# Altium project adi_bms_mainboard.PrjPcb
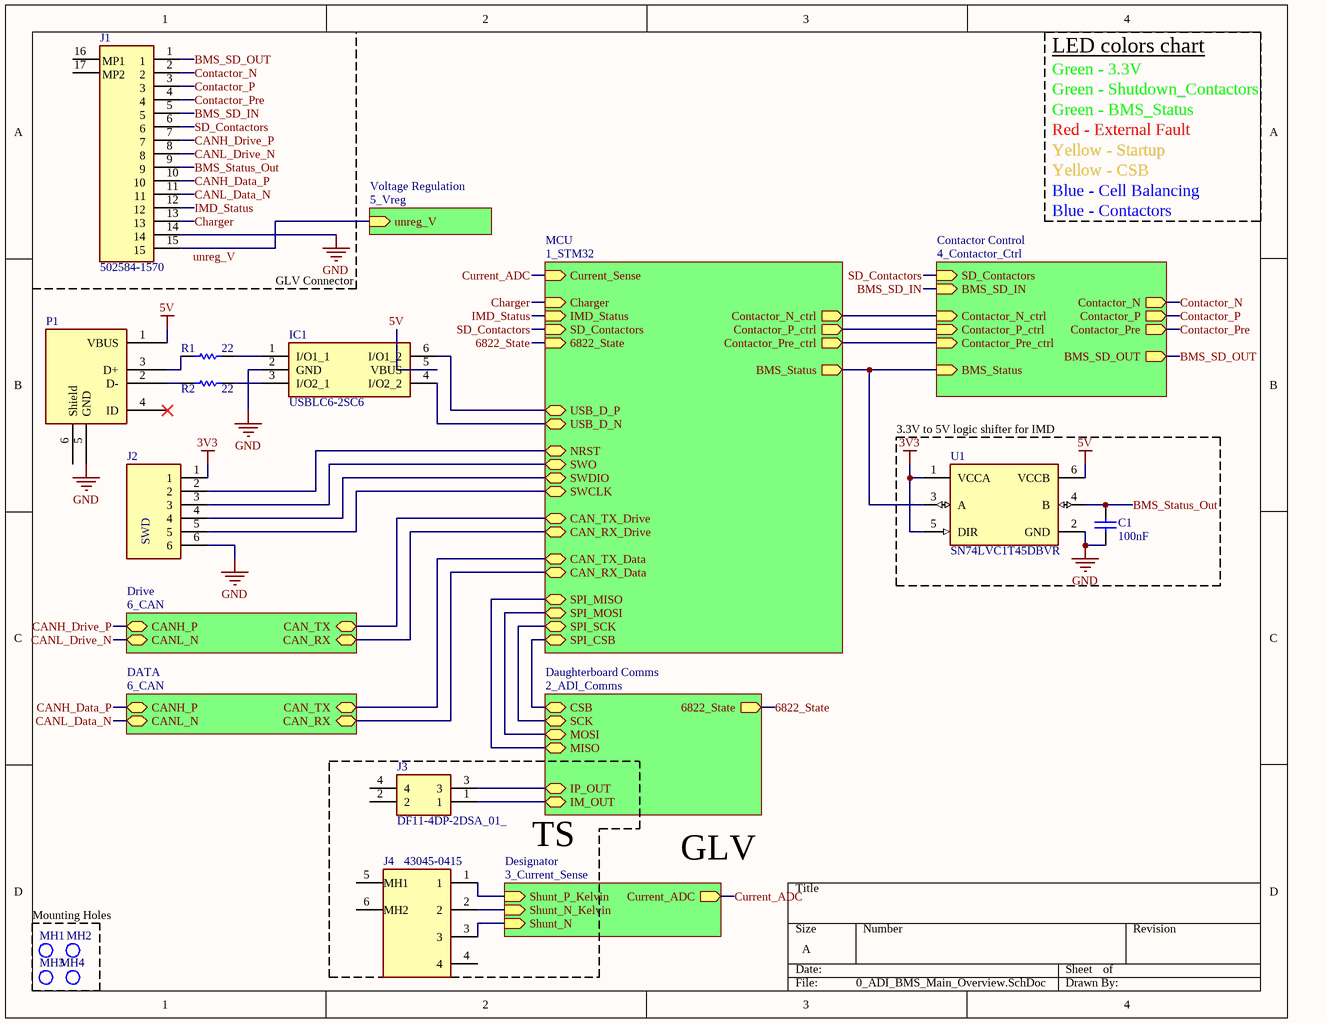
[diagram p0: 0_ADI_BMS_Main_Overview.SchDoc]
7 sheets, 187 parts. Net scope: hierarchical (ports join the sheet entries above them; power ports are global).
Board file: ad_mainboard.PcbDoc
Sheets:
  0_ADI_BMS_Main_Overview.SchDoc
    MCU = 1_STM32.SchDoc
    Contactor Control = 4_Contactor_Ctrl.SchDoc
    Daughterboard Comms = 2_ADI_Comms.SchDoc
    Designator = 3_Current_Sense.SchDoc
    Voltage Regulation = 5_Vreg.SchDoc
    Drive = 6_CAN.SchDoc
    DATA = 6_CAN.SchDoc

## Sheet 0_ADI_BMS_Main_Overview.SchDoc
size A

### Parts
C1  value 100nF  [CAPC0603(1608)100_L]  (hidden comment: CGA3E2X7R1H104K080AA)
IC1  USBLC6-2SC6  [SOT95P280X145-6N]
J1  502584-1570  [FP-502584-1570-MFG]
J2  61300611121  [HDRV6W64P0X254_1X6_1524X254X869P]  (value not drawn)
J3  DF11-4DP-2DSA_01_  [SHDR4W50P200_2X2_600X500X660P]
J4  43045-0415  [FP-43045-0415-MFG]
MH1  Mounting Hole 6-32 Non Plated  [Mounting Hole 6-32-Footprint-1]  (value not drawn)
MH2  Mounting Hole 6-32 Non Plated  [Mounting Hole 6-32-Footprint-1]  (value not drawn)
MH3  Mounting Hole 6-32 Non Plated  [Mounting Hole 6-32-Footprint-1]  (value not drawn)
MH4  Mounting Hole 6-32 Non Plated  [Mounting Hole 6-32-Footprint-1]  (value not drawn)
P1  1051640001  [1051640001-Footprint-1]  (value not drawn)
R1  value 22  [RESC0603(1608)_L]  (hidden comment: RC0603FR-0722RL)
R2  value 22  [RESC0603(1608)_L]  (hidden comment: RC0603FR-0722RL)
U1  SN74LVC1T45DBVR  [FP-DBV0006A-IPC_B]

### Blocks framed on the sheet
3.3V to 5V logic shifter for IMD: C1 U1
TS: J3 J4
Mounting Holes: MH1-MH4

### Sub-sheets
Contactor Control = 4_Contactor_Ctrl: SD_Contactors (in), Contactor_N_ctrl (in), Contactor_P_ctrl (in), Contactor_Pre_ctrl (in), BMS_Status (in), Contactor_N (out), Contactor_P (out), Contactor_Pre (out), BMS_SD_OUT (out), BMS_SD_IN (in)
DATA = 6_CAN: CAN_TX (bidir), CAN_RX (bidir), CANH_P (bidir), CANL_N (bidir)
Daughterboard Comms = 2_ADI_Comms: MISO (bidir), MOSI (bidir), SCK (bidir), CSB (bidir), 6822_State (out), IP_OUT (bidir), IM_OUT (bidir)
Designator = 3_Current_Sense: Shunt_P_Kelvin (in), Shunt_N_Kelvin (in), Shunt_N (in), Current_ADC (out)
Drive = 6_CAN: CAN_TX (bidir), CAN_RX (bidir), CANH_P (bidir), CANL_N (bidir)
MCU = 1_STM32: Current_Sense (in), Charger (in), IMD_Status (in), SD_Contactors (in), 6822_State (in), NRST (bidir), USB_D_N (bidir), USB_D_P (bidir), SWDIO (bidir), SWCLK (bidir), SWO (bidir), CAN_TX_Drive (bidir), CAN_RX_Drive (bidir), CAN_TX_Data (bidir), CAN_RX_Data (bidir), SPI_MISO (bidir), SPI_MOSI (bidir), SPI_SCK (bidir), SPI_CSB (bidir), BMS_Status (out), Contactor_N_ctrl (out), Contactor_P_ctrl (out), Contactor_Pre_ctrl (out)
Voltage Regulation = 5_Vreg: unreg_V (in)

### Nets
3V3: J2.1 U1.1(VCCA) U1.5(DIR)
5V: IC1.5(VBUS) P1.1(VBUS) U1.6(VCCB)
GND: C1.2 IC1.2(GND) J1.14 J2.6 P1.5(GND) U1.2(GND)
6822_State: sheet MCU/6822_State, sheet Daughterboard Comms/6822_State
BMS_SD_IN: J1.5 ; sheet Contactor Control/BMS_SD_IN
BMS_SD_OUT: J1.1 ; sheet Contactor Control/BMS_SD_OUT
BMS_Status: U1.3(A) ; sheet MCU/BMS_Status, sheet Contactor Control/BMS_Status
BMS_Status_Out: C1.1 J1.9 U1.4(B)
CAN_RX: sheet MCU/CAN_RX_Data, sheet DATA/CAN_RX
CAN_RX: sheet MCU/CAN_RX_Drive, sheet Drive/CAN_RX  [a separate net that carries the same name]
CAN_TX: sheet MCU/CAN_TX_Data, sheet DATA/CAN_TX
CAN_TX: sheet MCU/CAN_TX_Drive, sheet Drive/CAN_TX  [a separate net that carries the same name]
CANH_Data_P: J1.10 ; sheet DATA/CANH_P
CANH_Drive_P: J1.7 ; sheet Drive/CANH_P
CANL_Data_N: J1.11 ; sheet DATA/CANL_N
CANL_Drive_N: J1.8 ; sheet Drive/CANL_N
Charger: J1.13 ; sheet MCU/Charger
Contactor_N: J1.2 ; sheet Contactor Control/Contactor_N
Contactor_N_ctr: sheet MCU/Contactor_N_ctrl, sheet Contactor Control/Contactor_N_ctrl
Contactor_P: J1.3 ; sheet Contactor Control/Contactor_P
Contactor_P_ctrl: sheet MCU/Contactor_P_ctrl, sheet Contactor Control/Contactor_P_ctrl
Contactor_Pre: J1.4 ; sheet Contactor Control/Contactor_Pre
Contactor_Pre_ctr: sheet MCU/Contactor_Pre_ctrl, sheet Contactor Control/Contactor_Pre_ctrl
CSB: sheet MCU/SPI_CSB, sheet Daughterboard Comms/CSB
Current_ADC: sheet MCU/Current_Sense, sheet Designator/Current_ADC
IM_Out: J3.1 ; sheet Daughterboard Comms/IM_OUT
IMD_Status: J1.12 ; sheet MCU/IMD_Status
IP_Out: J3.3 ; sheet Daughterboard Comms/IP_OUT
MISO: sheet MCU/SPI_MISO, sheet Daughterboard Comms/MISO
MOSI: sheet MCU/SPI_MOSI, sheet Daughterboard Comms/MOSI
NRST: J2.2 ; sheet MCU/NRST
SCK: sheet MCU/SPI_SCK, sheet Daughterboard Comms/SCK
SD_Contactors: J1.6 ; sheet MCU/SD_Contactors, sheet Contactor Control/SD_Contactors
Shunt_N: J4.3 ; sheet Designator/Shunt_N
Shunt_N_Kelvin: J4.2 ; sheet Designator/Shunt_N_Kelvin
Shunt_P_Kelvin: J4.1 ; sheet Designator/Shunt_P_Kelvin
SWCLK: J2.5 ; sheet MCU/SWCLK
SWDIO: J2.4 ; sheet MCU/SWDIO
SWO: J2.3 ; sheet MCU/SWO
unreg_V: J1.15 ; sheet Voltage Regulation/unreg_V
USB_D_N: IC1.4(I/O2_2) ; sheet MCU/USB_D_N
USB_D_P: IC1.6(I/O1_2) ; sheet MCU/USB_D_P
NetIC1_1: IC1.1(I/O1_1) R1.2
NetIC1_3: IC1.3(I/O2_1) R2.2
NetP1_2: P1.2(D-) R2.1
NetP1_3: P1.3(D+) R1.1

Not connected (* = marked no-connect by the designer): J1 16(MNT_1) 17(MNT_2); J3 2 4; J4 4 5(MNT_1) 6(MNT_2); P1 4(ID)* 6(Shield)

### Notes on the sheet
- LED colors chart
- Green - 3.3V
- Green - Shutdown_Contactors
- Red - External Fault
- Green - BMS_Status
- Yellow - Startup
- Blue - Cell Balancing
- Yellow - CSB
- Blue - Contactors
- GLV Connector
- (near J2) SWD
- GLV

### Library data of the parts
C1 = CMP-001-00125-1: Ceramic Capacitor, Multilayer, Ceramic, 50V, 10% +Tol, 10% -Tol, X7R, 15% TC, 0.1uF, Surface Mount, 0603
IC1 = USBLC6-2SC6: Integrated Circuit; Manufacturer_Name: STMicroelectronics
J1 = CMP-002-00103-1: Board Connector, 15 Contact(s), 1 Row(s), Female, Straight, 0.059 inch Pitch, Surface Mount Terminal, Locking, Beige Insulator, Receptacle
J2 = 61300611121: Connector; Manufacturer_Name: Wurth Elektronik
J3 = DF11-4DP-2DSA_01_: Connector; Manufacturer_Name: Hirose; Manufacturer_Part_Number: DF11-4DP-2DSA(01)
J4 = CMP-002-00105-1: Rectangular Power Connector, 4 Contact(s), Male, Surface Mount Terminal, Receptacle; Connector Type: Power,Rectangular
MH1-MH4 = CMP-00028-00008-4: Mounting hole for 6-32 fastener
P1 = CMP-002-00079-1: USB - micro B USB 2.0 Receptacle Connector 5 Position Surface Mount, Right Angle; Through Hole
R1 R2 = CMP-009-00242-1: Fixed Resistor, Metal Glaze/thick Film, 0.1W, 22ohm, 75V, 1% +/-Tol, 100ppm/Cel, Surface Mount, 0603; Power: 100mW
U1 = CMP-0859-00206-4: IC TRNSLTR BIDIRECTIONAL SOT23-6; Number of Inputs: 1; Logic Function: Translator; Min Supply Voltage: 1.65V; Quiescent Current: 3uA; Turn-On Delay Time: 36.2ns; Max Supply Voltage: 5.5V; Polarity: Non-Inverting; Propagation Delay: 3.9ns; Low Level Output Current: 32mA; Data Rate: 420Mbps; High Level Output Current: -32mA

## Sheet 1_STM32.SchDoc
size A
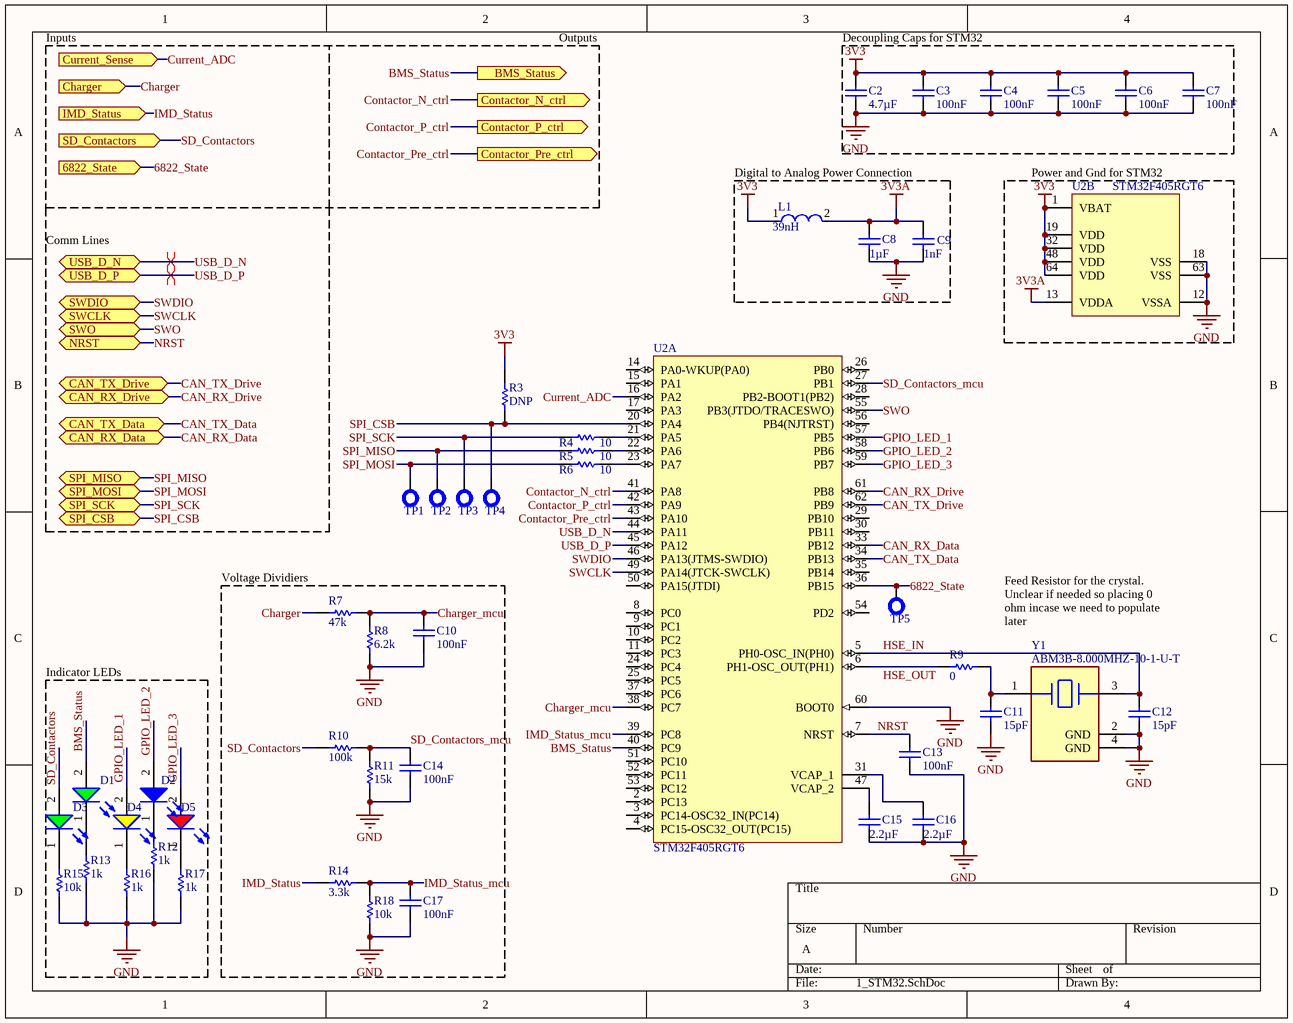
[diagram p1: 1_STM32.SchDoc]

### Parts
C2  value 4.7µF  [CAPC0603(1608)100_L]  (hidden comment: GRT188R6YA475KE13D)
C3  value 100nF  [CAPC0603(1608)100_L]  (hidden comment: CGA3E2X7R1H104K080AA)
C4  value 100nF  [CAPC0603(1608)100_L]  (hidden comment: CGA3E2X7R1H104K080AA)
C5  value 100nF  [CAPC0603(1608)100_L]  (hidden comment: CGA3E2X7R1H104K080AA)
C6  value 100nF  [CAPC0603(1608)100_L]  (hidden comment: CGA3E2X7R1H104K080AA)
C7  value 100nF  [CAPC0603(1608)100_L]  (hidden comment: CGA3E2X7R1H104K080AA)
C8  value 1µF  [CAPC0603(1608)100_L]  (hidden comment: GRT188R61H105KE13D)
C9  1nF  [CAPC0603(1608)100_L]
C10  value 100nF  [CAPC0603(1608)100_L]  (hidden comment: CGA3E2X7R1H104K080AA)
C11  value 15pF  [CAPC0603(1608)100_L]  (hidden comment: CL10C150JB81PNC)
C12  value 15pF  [CAPC0603(1608)100_L]  (hidden comment: CL10C150JB81PNC)
C13  value 100nF  [CAPC0603(1608)100_L]  (hidden comment: CGA3E2X7R1H104K080AA)
C14  value 100nF  [CAPC0603(1608)100_L]  (hidden comment: CGA3E2X7R1H104K080AA)
C15  value 2.2µF  [CAPC0603(1608)100_L]  (hidden comment: CL10Y225KP84PNC)
C16  value 2.2µF  [CAPC0603(1608)100_L]  (hidden comment: CL10Y225KP84PNC)
C17  value 100nF  [CAPC0603(1608)100_L]  (hidden comment: CGA3E2X7R1H104K080AA)
D1  150060VS75000  [WL-SMCW_0603_150060xx75000]  (value not drawn)
D2  150060BS75000  [WL-SMCW_0603_150060xx75000]  (value not drawn)
D3  150060VS75000  [WL-SMCW_0603_150060xx75000]  (value not drawn)
D4  150060YS75000  [WL-SMCW_0603_150060xx75000]  (value not drawn)
D5  150060RS75000  [WL-SMCW_0603_150060xx75000]  (value not drawn)
L1  Inductance: 39nH  [FP-LQW18AN_00-MFG]  (hidden comment: LQW18AN39NJ00D)
R3  value DNP  [RESC0603(1608)_L]  (hidden comment: RT0603BRD0710KL)
R4  value 10  [RESC0603(1608)_L]  (hidden comment: RMCF0603FT10R0)
R5  value 10  [RESC0603(1608)_L]  (hidden comment: RMCF0603FT10R0)
R6  value 10  [RESC0603(1608)_L]  (hidden comment: RMCF0603FT10R0)
R7  value 47k  [RESC0603(1608)_L]  (hidden comment: ERA-3AEB473V)
R8  value 6.2k  [RESC0603(1608)_L]  (hidden comment: ERA-3AEB622V)
R9  value 0  [RESC0603(1608)_L]  (hidden comment: RMCF0603ZT0R00)
R10  value 100k  [RESC0603(1608)_L]  (hidden comment: ERJ-3EKF1003V)
R11  value 15k  [RESC0603(1608)_L]  (hidden comment: ERA-3AEB153V)
R12  value 1k  [RESC0603(1608)_L]  (hidden comment: RMCF0603FT1K00)
R13  value 1k  [RESC0603(1608)_L]  (hidden comment: RMCF0603FT1K00)
R14  value 3.3k  [RESC0603(1608)_L]  (hidden comment: ERA-3AEB332V)
R15  value 10k  [RESC0603(1608)_L]  (hidden comment: RT0603BRD0710KL)
R16  value 1k  [RESC0603(1608)_L]  (hidden comment: RMCF0603FT1K00)
R17  value 1k  [RESC0603(1608)_L]  (hidden comment: RMCF0603FT1K00)
R18  value 10k  [RESC0603(1608)_L]  (hidden comment: RT0603BRD0710KL)
TP1  TEST_POINT_40_MIL  [TEST_POINT_40_MIL-Footprint-1]  (value not drawn)
TP2  TEST_POINT_40_MIL  [TEST_POINT_40_MIL-Footprint-1]  (value not drawn)
TP3  TEST_POINT_40_MIL  [TEST_POINT_40_MIL-Footprint-1]  (value not drawn)
TP4  TEST_POINT_40_MIL  [TEST_POINT_40_MIL-Footprint-1]  (value not drawn)
TP5  TEST_POINT_40_MIL  [TEST_POINT_40_MIL-Footprint-1]  (value not drawn)
U2  STM32F405RGT6  [STM-LQFP64_M]  (parts A,B of 2)
Y1  ABM3B-8.000MHZ-10-1-U-T  [FP-ABM3B-MFG]

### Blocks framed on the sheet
Decoupling Caps for STM32: C2-C7
Digital to Analog Power Connection: C8 C9 L1
Power and Gnd for STM32: U2
Voltage Dividiers: C10 C14 C17 R7 R8 R10 R11 R14 R18
Indicator LEDs: D1-D5 R12 R13 R15-R17

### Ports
6822_State (in), BMS_Status (out), CAN_RX_Data (bidir), CAN_RX_Drive (bidir), CAN_TX_Data (bidir), CAN_TX_Drive (bidir), Charger (in), Contactor_N_ctrl (out), Contactor_P_ctrl (out), Contactor_Pre_ctrl (out), Current_Sense (in), IMD_Status (in), NRST (bidir), SD_Contactors (in), SPI_CSB (bidir), SPI_MISO (bidir), SPI_MOSI (bidir), SPI_SCK (bidir), SWCLK (bidir), SWDIO (bidir), SWO (bidir), USB_D_N (bidir), USB_D_P (bidir)

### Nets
3V3: C2.2 C3.1 C4.1 C5.1 C6.1 C7.1 L1.1 R3.2 U2.1(VBAT) U2.19(VDD) U2.32(VDD) U2.48(VDD) U2.64(VDD)
3V3A: C8.2 C9.2 L1.2 U2.13(VDDA)
GND: C2.1 C3.2 C4.2 C5.2 C6.2 C7.2 C8.1 C9.1 C10.2 C11.1 C12.1 C13.2 C14.2 C15.2 C16.2 C17.2 R8.2 R11.1 R12.1 R13.1 R15.1 R16.1 R17.1 R18.1 U2.12(VSSA) U2.18(VSS) U2.60(BOOT0) U2.63(VSS) Y1.2(GND) Y1.4(GND)
6822_State: TP5.1 U2.36(PB15) ; port 6822_State
BMS_Status: D1.2(A) U2.40(PC9) ; port BMS_Status
CAN_RX_Data: U2.33(PB12) ; port CAN_RX_Data  [project net CAN_RX]
CAN_RX_Drive: U2.61(PB8) ; port CAN_RX_Drive  [project net CAN_RX]
CAN_TX_Data: U2.34(PB13) ; port CAN_TX_Data  [project net CAN_TX]
CAN_TX_Drive: U2.62(PB9) ; port CAN_TX_Drive  [project net CAN_TX]
Charger: R7.2 ; port Charger
Charger_mcu: C10.1 R7.1 R8.1 U2.38(PC7)
Contactor_N_ctrl: U2.41(PA8) ; port Contactor_N_ctrl  [project net Contactor_N_ctr]
Contactor_P_ctrl: U2.42(PA9) ; port Contactor_P_ctrl
Contactor_Pre_ctrl: U2.43(PA10) ; port Contactor_Pre_ctrl  [project net Contactor_Pre_ctr]
Current_ADC: U2.16(PA2) ; port Current_Sense
GPIO_LED_1: D4.2(A) U2.57(PB5)
GPIO_LED_2: D2.2(A) U2.58(PB6)
GPIO_LED_3: D5.2(A) U2.59(PB7)
HSE_IN: C12.2 U2.5(PH0-OSC_IN(PH0)) Y1.3
HSE_OUT: R9.2 U2.6(PH1-OSC_OUT(PH1))
IMD_Status: R14.2 ; port IMD_Status
IMD_Status_mcu: C17.1 R14.1 R18.2 U2.39(PC8)
NRST: C13.1 U2.7(NRST) ; port NRST
SD_Contactors: D3.2(A) R10.1 ; port SD_Contactors
SD_Contactors_mcu: C14.1 R10.2 R11.2 U2.27(PB1)
SPI_CSB: R3.1 TP4.1 U2.20(PA4) ; port SPI_CSB  [project net CSB]
SPI_MISO: R5.1 TP2.1 ; port SPI_MISO  [project net MISO]
SPI_MOSI: R6.1 TP1.1 ; port SPI_MOSI  [project net MOSI]
SPI_SCK: R4.1 TP3.1 ; port SPI_SCK  [project net SCK]
SWCLK: U2.49(PA14(JTCK-SWCLK)) ; port SWCLK
SWDIO: U2.46(PA13(JTMS-SWDIO)) ; port SWDIO
SWO: U2.55(PB3(JTDO/TRACESWO)) ; port SWO
USB_D_N: U2.44(PA11) ; port USB_D_N
USB_D_P: U2.45(PA12) ; port USB_D_P
NetC11_2: C11.2 R9.1 Y1.1
NetC15_1: C15.1 U2.47(VCAP_2)
NetC16_1: C16.1 U2.31(VCAP_1)
NetD1_1: D1.1(K) R13.2
NetD2_1: D2.1(K) R12.2
NetD3_1: D3.1(K) R15.2
NetD4_1: D4.1(K) R16.2
NetD5_1: D5.1(K) R17.2
NetR4_2: R4.2 U2.21(PA5)
NetR5_2: R5.2 U2.22(PA6)
NetR6_2: R6.2 U2.23(PA7)

Not connected (* = marked no-connect by the designer): U2 2(PC13) 3(PC14-OSC32_IN(PC14)) 4(PC15-OSC32_OUT(PC15)) 8(PC0) 9(PC1) 10(PC2) 11(PC3) 14(PA0-WKUP(PA0)) 15(PA1) 17(PA3) 24(PC4) 25(PC5) 26(PB0) 28(PB2-BOOT1(PB2)) 29(PB10) 30(PB11) 35(PB14) 37(PC6) 50(PA15(JTDI)) 51(PC10) 52(PC11) 53(PC12) 54(PD2) 56(PB4(NJTRST))

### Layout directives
differential pair: USB_D_N, USB_D_P

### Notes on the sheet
- Inputs
- Outputs
- Comm Lines
- Feed Resistor for the crystal. Unclear if needed so placing 0 ohm incase we need to populate later

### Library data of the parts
C2 = CMP-001-00126-1: Ceramic Capacitor, Multilayer, Ceramic, 35V, 10% +Tol, 10% -Tol, X5R, 15% TC, 4.7uF, Surface Mount, 0603
C3-C7 C10 C13 C14 C17 = CMP-001-00125-1: as C1 on sheet 0_ADI_BMS_Main_Overview
C8 = CMP-001-00128-1: Ceramic Capacitor, Multilayer, Ceramic, 50V, 10% +Tol, 10% -Tol, X5R, 15% TC, 1uF, Surface Mount, 0603
C9 = CMP-001-00094-1: Ceramic Capacitor, Ceramic, 1 nF, CL10B102KB8WPJC
C11 C12 = CMP-001-00113-1: Ceramic Capacitor, Multilayer, Ceramic, 50V, 5% +Tol, 5% -Tol, C0G, -/+30ppm/Cel TC, 0.000015uF, Surface Mount, 0603
C15 C16 = CMP-001-00112-1: Ceramic Capacitor, Multilayer, Ceramic, 10V, 10% +Tol, 10% -Tol, X7S, 22% TC, 2.2uF, Surface Mount, 0603
D1 D3 = CMP-1426-00006-7: WURTH ELEKTRONIK - 150060VS75000 - LED, Green, SMD, 0603, 30 mA, 2 V, 570 nm; Reverse Voltage: 5V; Power Dissipation: 72mW; Dominant Wavelength: 570nm; Peak Wavelength: 572nm; Forward Current: 100mA; Forward Voltage: 2V; Lens Style: Clear, Rectangular; Test Current: 20mA; Max Junction Temperature (Tj): 95°C; Viewing Angle: 140°; Luminous Intensity: 40mcd
D2 = CMP-1426-00003-4: Led, Blue, 470 Nm, 3.2 V, 30 Ma, 145 Mcd Rohs Compliant: Yes; Peak Wavelength: 465nm; Dominant Wavelength: 470nm; Power Dissipation: 105mW; Viewing Angle: 140°; Test Current: 20mA; Max Junction Temperature (Tj): 95°C; Forward Current: 100mA; Reverse Voltage: 5V; Luminous Intensity: 145mcd; Lens Style: Clear, Rectangular; Forward Voltage: 3.2V
D4 = CMP-1426-00005-3: WL-SMCW SMT Mono-Color Chip LED Waterclear; Power Dissipation: 72mW; Reverse Voltage: 5V; Forward Voltage: 2V; Test Current: 20mA; Luminous Intensity: 120mcd; Max Junction Temperature (Tj): 95°C; Wavelength: 590nm; Color: Yellow; Forward Current: 100mA; Lens Style: Clear, Rectangular; Viewing Angle: 140°; Peak Wavelength: 595nm
D5 = CMP-1426-00001-4: LED Low-Power Uni-Color Red 630nm 2V 2-Pin Chip 0603(1608Metric) T/R; Max Junction Temperature (Tj): 95°C; Dominant Wavelength: 625nm; Lens Style: Clear, Rectangular; Viewing Angle: 140°; Forward Current: 100mA; Max Reverse Voltage (DC): 5V; Luminous Intensity: 250mcd; Test Current: 20mA; Power Dissipation: 72mW
L1 = CMP-06042-014671-1: Wire Wound RF Inductor 39nH ±5% 400mA 0.26Ω 0603 (1608); Test Frequency: 100MHz; Shielding: Unshielded; Self Resonant Frequency: 2.8GHz; Core Material: Non-Magnetic; DC Resistance (DCR): 260mR; Q Factor: 40
R3 R15 R18 = CMP-009-00204-1: Fixed Resistor, Thin Film, 0.1W, 10000ohm, 75V, 0.1% +/-Tol, 25ppm/Cel, Surface Mount, 0603; Power: 100mW
R4-R6 = CMP-009-00257-1: Fixed Resistor, Metal Glaze/thick Film, 0.1W, 10ohm, 75V, 1% +/-Tol, 100ppm/Cel, Surface Mount, 0603; Power: 100mW
R7 = CMP-009-00259-1: Fixed Resistor, Thin Film, 0.1W, 47000ohm, 75V, 0.1% +/-Tol, 25ppm/Cel, Surface Mount, 0603; Power: 100mW
R8 = CMP-009-00261-1: Fixed Resistor, Thin Film, 0.1W, 6200ohm, 75V, 0.1% +/-Tol, 25ppm/Cel, Surface Mount, 0603; Power: 100mW
R9 = CMP-009-00243-1: Fixed Resistor, Metal Glaze/thick Film, 0.1W, 0ohm, Surface Mount, 0603; Power: 100mW
R10 = CMP-009-00221-2: Fixed Resistor, Metal Glaze/thick Film, 0.1W, 100000ohm, 75V, 1% +/-Tol, 100ppm/Cel, Surface Mount, 0603; Power: 100mW
R11 = CMP-009-00220-2: Fixed Resistor, Thin Film, 0.1W, 15000ohm, 75V, 0.1% +/-Tol, 25ppm/Cel, Surface Mount, 0603; Power: 100mW
R12 R13 R16 R17 = CMP-009-00263-1: Fixed Resistor, Metal Glaze/thick Film, 0.1W, 1000ohm, 75V, 1% +/-Tol, 100ppm/Cel, Surface Mount, 0603; Power: 100mW
R14 = CMP-009-00260-1: Fixed Resistor, Thin Film, 0.1W, 3300ohm, 75V, 0.1% +/-Tol, 25ppm/Cel, Surface Mount, 0603; Power: 100mW
TP1-TP5 = CMP-001-0000-1: 40 mil diameter test point
U2 = CMP-0243-00019-3: ARM Cortex-M4 32-bit MCU+FPU, 210 DMIPS, 1024 kB Flash, 192 kB Internal RAM, 51 I/Os, 64-pin LQFP, -40 to 85 degC, Tray; Manufacturer: STMicroelectronics; Supply Voltage(Vcc) min (V): 1.8; Supply Voltage(Vcc) max (V): 3.6; Internal RAM Size (kB): 192; I/Os (High Current): 51; D/A Converter: 2x12-bit; FLASH Size (Prog) (kB): 1024; Operating Frequency(F) (Processor speed) (MHz): 168
Y1 = CMP-2000-05730-2: Crystal 8MHz ±10ppm 10pF SMD-4 5mm x 3.2mm; Series Resistance: 200R

## Sheet 4_Contactor_Ctrl.SchDoc
size A
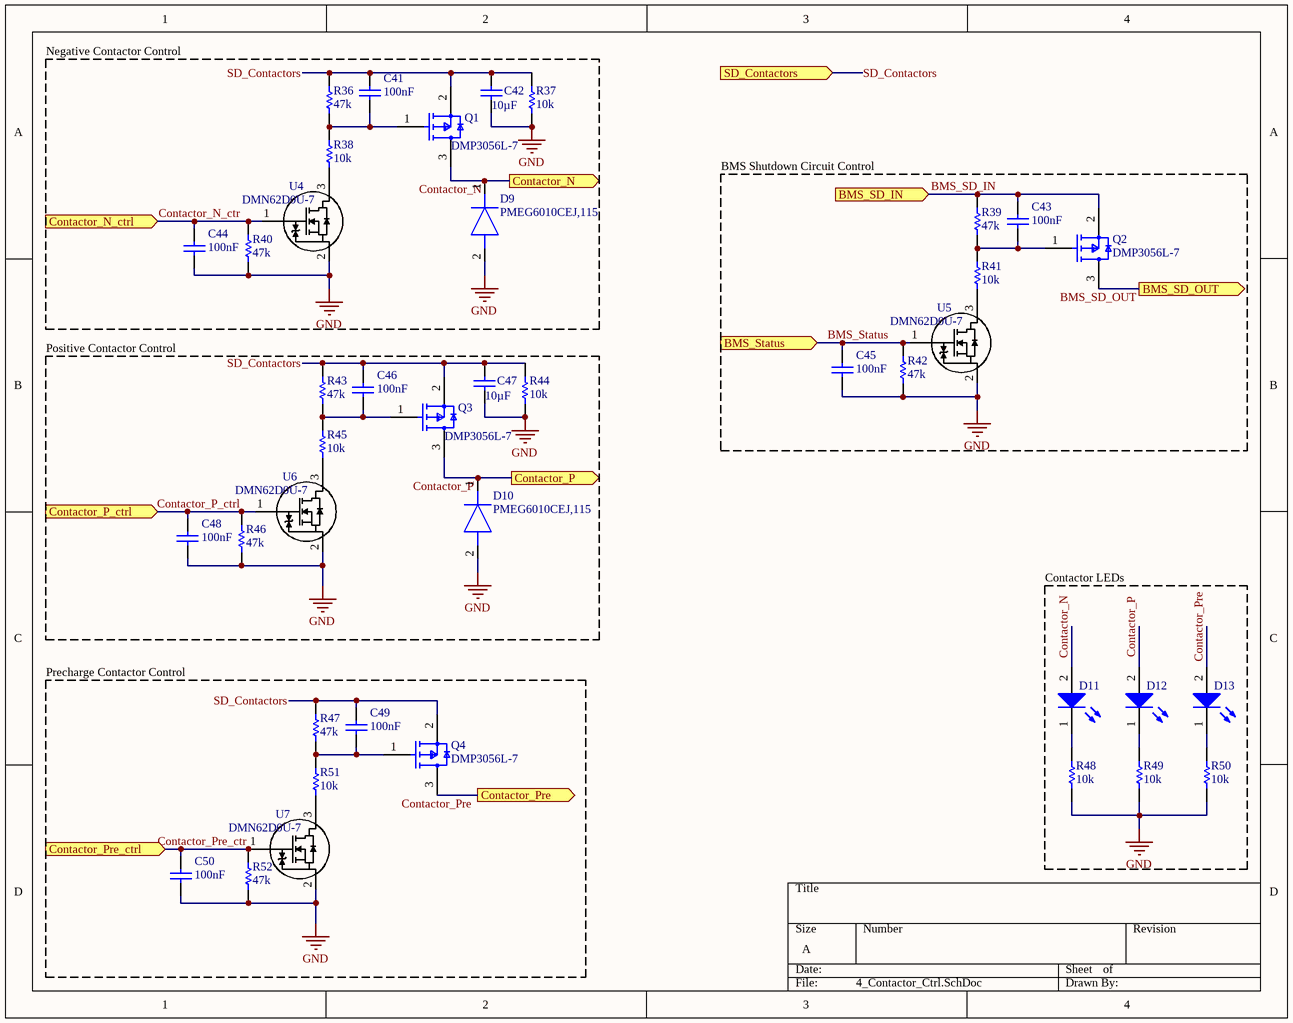
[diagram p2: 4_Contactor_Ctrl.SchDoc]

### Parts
C41  value 100nF  [CAPC0603(1608)100_L]  (hidden comment: CGA3E2X7R1H104K080AA)
C42  value 10µF  [CAPC0603(1608)100_L]  (hidden comment: GRM188R6YA106MA73D)
C43  value 100nF  [CAPC0603(1608)100_L]  (hidden comment: CGA3E2X7R1H104K080AA)
C44  value 100nF  [CAPC0603(1608)100_L]  (hidden comment: CGA3E2X7R1H104K080AA)
C45  value 100nF  [CAPC0603(1608)100_L]  (hidden comment: CGA3E2X7R1H104K080AA)
C46  value 100nF  [CAPC0603(1608)100_L]  (hidden comment: CGA3E2X7R1H104K080AA)
C47  value 10µF  [CAPC0603(1608)100_L]  (hidden comment: GRM188R6YA106MA73D)
C48  value 100nF  [CAPC0603(1608)100_L]  (hidden comment: CGA3E2X7R1H104K080AA)
C49  value 100nF  [CAPC0603(1608)100_L]  (hidden comment: CGA3E2X7R1H104K080AA)
C50  value 100nF  [CAPC0603(1608)100_L]  (hidden comment: CGA3E2X7R1H104K080AA)
D9  PMEG6010CEJ,115  [SODFL2512X80N]
D10  PMEG6010CEJ,115  [SODFL2512X80N]
D11  150060BS75000  [WL-SMCW_0603_150060xx75000]  (value not drawn)
D12  150060BS75000  [WL-SMCW_0603_150060xx75000]  (value not drawn)
D13  150060BS75000  [WL-SMCW_0603_150060xx75000]  (value not drawn)
Q1  DMP3056L-7  [FP-SOT23-MFG]
Q2  DMP3056L-7  [FP-SOT23-MFG]
Q3  DMP3056L-7  [FP-SOT23-MFG]
Q4  DMP3056L-7  [FP-SOT23-MFG]
R36  value 47k  [RESC0603(1608)_L]  (hidden comment: ERA-3AEB473V)
R37  value 10k  [RESC0603(1608)_L]  (hidden comment: RT0603BRD0710KL)
R38  value 10k  [RESC0603(1608)_L]  (hidden comment: RT0603BRD0710KL)
R39  value 47k  [RESC0603(1608)_L]  (hidden comment: ERA-3AEB473V)
R40  value 47k  [RESC0603(1608)_L]  (hidden comment: ERA-3AEB473V)
R41  value 10k  [RESC0603(1608)_L]  (hidden comment: RT0603BRD0710KL)
R42  value 47k  [RESC0603(1608)_L]  (hidden comment: ERA-3AEB473V)
R43  value 47k  [RESC0603(1608)_L]  (hidden comment: ERA-3AEB473V)
R44  value 10k  [RESC0603(1608)_L]  (hidden comment: RT0603BRD0710KL)
R45  value 10k  [RESC0603(1608)_L]  (hidden comment: RT0603BRD0710KL)
R46  value 47k  [RESC0603(1608)_L]  (hidden comment: ERA-3AEB473V)
R47  value 47k  [RESC0603(1608)_L]  (hidden comment: ERA-3AEB473V)
R48  value 10k  [RESC0603(1608)_L]  (hidden comment: RT0603BRD0710KL)
R49  value 10k  [RESC0603(1608)_L]  (hidden comment: RT0603BRD0710KL)
R50  value 10k  [RESC0603(1608)_L]  (hidden comment: RT0603BRD0710KL)
R51  value 10k  [RESC0603(1608)_L]  (hidden comment: RT0603BRD0710KL)
R52  value 47k  [RESC0603(1608)_L]  (hidden comment: ERA-3AEB473V)
U4  DMN62D0U-7  [SOT23_DMN62D0U-7_DIO]
U5  DMN62D0U-7  [SOT23_DMN62D0U-7_DIO]
U6  DMN62D0U-7  [SOT23_DMN62D0U-7_DIO]
U7  DMN62D0U-7  [SOT23_DMN62D0U-7_DIO]

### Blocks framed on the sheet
Negative Contactor Control: C41 C42 C44 D9 Q1 R36-R38 R40 U4
BMS Shutdown Circuit Control: C43 C45 Q2 R39 R41 R42 U5
Positive Contactor Control: C46-C48 D10 Q3 R43-R46 U6
Contactor LEDs: D11-D13 R48-R50
Precharge Contactor Control: C49 C50 Q4 R47 R51 R52 U7

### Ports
BMS_SD_IN (in), BMS_SD_OUT (out), BMS_Status (in), Contactor_N (out), Contactor_N_ctrl (in), Contactor_P (out), Contactor_P_ctrl (in), Contactor_Pre (out), Contactor_Pre_ctrl (in), SD_Contactors (in)

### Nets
GND: C42.1 C44.1 C45.1 C47.1 C48.1 C50.1 D9.2(A) D10.2(A) R37.1 R40.1 R42.1 R44.1 R46.1 R48.1 R49.1 R50.1 R52.1 U4.2(S) U5.2(S) U6.2(S) U7.2(S)
BMS_SD_IN: C43.2 Q2.2(S) R39.2 ; port BMS_SD_IN
BMS_SD_OUT: Q2.3(D) ; port BMS_SD_OUT
BMS_Status: C45.2 R42.2 U5.1(G) ; port BMS_Status
Contactor_N: D9.1(K) D11.2(A) Q1.3(D) ; port Contactor_N
Contactor_N_ctr: C44.2 R40.2 U4.1(G) ; port Contactor_N_ctrl
Contactor_P: D10.1(K) D12.2(A) Q3.3(D) ; port Contactor_P
Contactor_P_ctrl: C48.2 R46.2 U6.1(G) ; port Contactor_P_ctrl
Contactor_Pre: D13.2(A) Q4.3(D) ; port Contactor_Pre
Contactor_Pre_ctr: C50.2 R52.2 U7.1(G) ; port Contactor_Pre_ctrl
SD_Contactors: C41.2 C42.2 C46.2 C47.2 C49.2 Q1.2(S) Q3.2(S) Q4.2(S) R36.2 R37.2 R43.2 R44.2 R47.2 ; port SD_Contactors
NetC41_1: C41.1 Q1.1(G) R36.1 R38.2
NetC43_1: C43.1 Q2.1(G) R39.1 R41.2
NetC46_1: C46.1 Q3.1(G) R43.1 R45.2
NetC49_1: C49.1 Q4.1(G) R47.1 R51.2
NetD11_1: D11.1(K) R48.2
NetD12_1: D12.1(K) R49.2
NetD13_1: D13.1(K) R50.2
NetR38_1: R38.1 U4.3(D)
NetR41_1: R41.1 U5.3(D)
NetR45_1: R45.1 U6.3(D)
NetR51_1: R51.1 U7.3(D)

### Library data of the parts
C41 C43-C46 C48-C50 = CMP-001-00125-1: as C1 on sheet 0_ADI_BMS_Main_Overview
C42 C47 = CMP-001-00133-1: Ceramic Capacitor, Multilayer, Ceramic, 35V, 20% +Tol, 20% -Tol, X5R, 15% TC, 10uF, Surface Mount, 0603
D9 D10 = PMEG6010CEJ,115: Diode; Manufacturer_Name: Nexperia
D11-D13 = CMP-1426-00003-4: as D2 on sheet 1_STM32
Q1-Q4 = CMP-12801-000002-1: MOSFET P-CH 30V 4.3A SOT23; Manufacturer: Diodes Inc.; Rthja Max: 91°C/W; Drain To Source Resistance: 35mΩ; Turn Off Delay Time: 35.2ns; Depletion Mode: False; Threshold Vgs Max: -2.1V; Drain To Source Voltage: -30V; Turn On Delay Time: 4.9ns; Max Forward Diode Voltage: -1.2V; Pulse Drain Current: -20A; Standoff Height: 0.013mm; Power Dissipation: 1.38W; Max Junction Temp: +150°C; Gate To Source Voltage: 25V; Continuous Drain Current: -4.3A; Number Of P Channels: 1; Input Capacitace At Vds: 642pF @ -25V; Automotive Grade: NA; Threshold Vgs Min: -1V; Gate Charge At Vgs: 11.8nC @ -10V
R36 R39 R40 R42 R43 R46 R47 R52 = CMP-009-00259-1: as R7 on sheet 1_STM32
R37 R38 R41 R44 R45 R48-R51 = CMP-009-00204-1: as R3 on sheet 1_STM32
U4-U7 = CMP-011-000000-2: N-CH MOSFET; Mfr_Name: Diodes Inc

## Sheet 2_ADI_Comms.SchDoc
size A
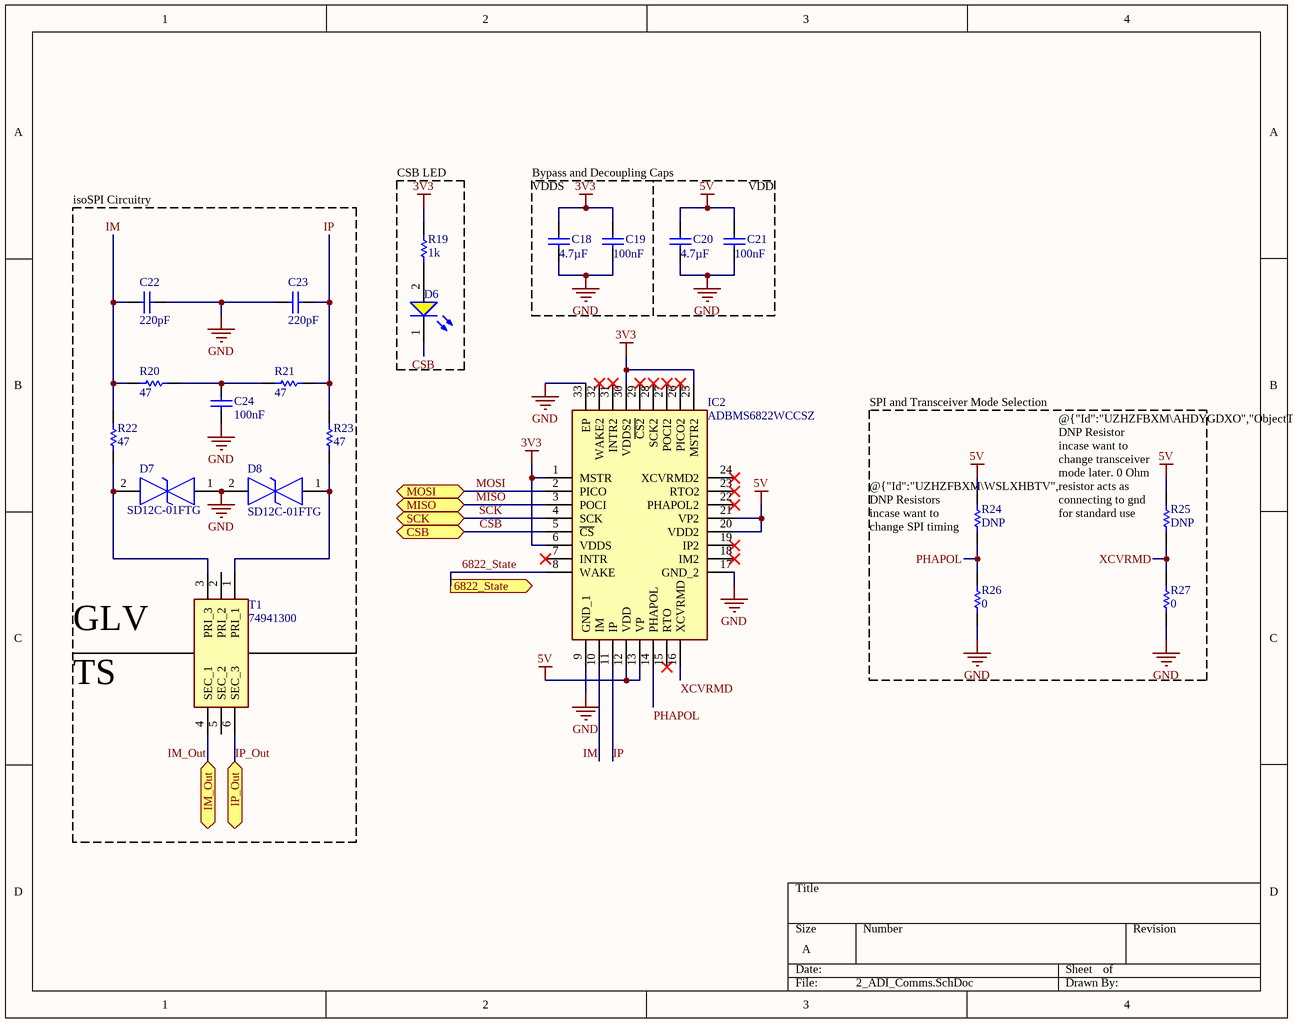
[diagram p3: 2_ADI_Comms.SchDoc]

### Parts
C18  value 4.7µF  [CAPC0603(1608)100_L]  (hidden comment: GRT188R6YA475KE13D)
C19  value 100nF  [CAPC0603(1608)100_L]  (hidden comment: CGA3E2X7R1H104K080AA)
C20  value 4.7µF  [CAPC0603(1608)100_L]  (hidden comment: GRT188R6YA475KE13D)
C21  value 100nF  [CAPC0603(1608)100_L]  (hidden comment: CGA3E2X7R1H104K080AA)
C22  value 220pF  [CAPC0603(1608)100_L]  (hidden comment: CGA3E2C0G2A221J080AA)
C23  value 220pF  [CAPC0603(1608)100_L]  (hidden comment: CGA3E2C0G2A221J080AA)
C24  value 100nF  [CAPC0603(1608)100_L]  (hidden comment: CGA3E2X7R1H104K080AA)
D6  150060YS75000  [WL-SMCW_0603_150060xx75000]  (value not drawn)
D7  SD12C-01FTG  [SOD2613X114N]
D8  SD12C-01FTG  [SOD2613X114N]
IC2  ADBMS6822WCCSZ  [QFN50P500X500X80-33N-D]
R19  value 1k  [RESC0603(1608)_L]  (hidden comment: RMCF0603FT1K00)
R20  value 47  [RESC0603(1608)_L]  (hidden comment: ESR03EZPJ470)
R21  value 47  [RESC0603(1608)_L]  (hidden comment: ESR03EZPJ470)
R22  value 47  [RESC0603(1608)_L]  (hidden comment: ESR03EZPJ470)
R23  value 47  [RESC0603(1608)_L]  (hidden comment: ESR03EZPJ470)
R24  value DNP  [RESC0603(1608)_L]  (hidden comment: RMCF0603ZT0R00)
R25  value DNP  [RESC0603(1608)_L]  (hidden comment: RMCF0603ZT0R00)
R26  value 0  [RESC0603(1608)_L]  (hidden comment: RMCF0603ZT0R00)
R27  value 0  [RESC0603(1608)_L]  (hidden comment: RMCF0603ZT0R00)
T1  74941300  [74941300]

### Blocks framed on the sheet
CSB LED: D6 R19
SPI and Transceiver Mode Selection: R24-R27

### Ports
6822_State (out), CSB (bidir), IM_Out (bidir), IP_Out (bidir), MISO (bidir), MOSI (bidir), SCK (bidir)

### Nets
3V3: C18.2 C19.1 IC2.1(MSTR) IC2.6(VDDS) IC2.25(MSTR2) IC2.30(VDDS2) R19.2
5V: C20.2 C21.1 IC2.12(VDD) IC2.13(VP) IC2.20(VDD2) IC2.21(VP2) R24.2 R25.2
GND: C18.1 C19.2 C20.1 C21.2 C22.2 C23.1 C24.2 D7.1 D8.2 IC2.9(GND_1) IC2.17(GND_2) IC2.33(EP) R26.2 R27.1
6822_State: IC2.8(WAKE) ; port 6822_State
CSB: D6.1(K) IC2.5(~{CS}) ; port CSB
IM: C22.1 IC2.10(IM) R20.2 R22.2
IM_Out: T1.4(SEC_1) ; port IM_Out
IP: C23.2 IC2.11(IP) R21.1 R23.2
IP_Out: T1.6(SEC_3) ; port IP_Out
MISO: IC2.3(POCI) ; port MISO
MOSI: IC2.2(PICO) ; port MOSI
PHAPOL: IC2.14(PHAPOL) R24.1 R26.1
SCK: IC2.4(SCK) ; port SCK
XCVRMD: IC2.16(XCVRMD) R25.1 R27.2
NetC24_1: C24.1 R20.1 R21.2
NetD6_2: D6.2(A) R19.1
NetD7_2: D7.2 R22.1 T1.3(PRI_3)
NetD8_1: D8.1 R23.1 T1.1(PRI_1)

Not connected (* = marked no-connect by the designer): IC2 7(INTR)* 15(RTO)* 18(IM2)* 19(IP2)* 22(PHAPOL2)* 23(RTO2)* 24(XCVRMD2)* 26(PICO2)* 27(POCI2)* 28(SCK2)* 29(~{CS2})* 31(INTR2)* 32(WAKE2)*; T1 2(PRI_2) 5(SEC_2)

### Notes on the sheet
- isoSPI Circuitry
- Bypass and Decoupling Caps
- (near C18) VDDS
- (near C21) VDD
- (near R24) @{"Id":"UZHZFBXM\WSLXHBTV","ObjectType":1} DNP Resistors incase want to change SPI timing later
- (near R25) @{"Id":"UZHZFBXM\AHDYGDXO","ObjectType":1} DNP Resistor incase want to change transceiver mode later. 0 Ohm resistor acts as connecting to gnd for standard use
- GLV
- TS

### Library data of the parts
C18 C20 = CMP-001-00126-1: as C2 on sheet 1_STM32
C19 C21 C24 = CMP-001-00125-1: as C1 on sheet 0_ADI_BMS_Main_Overview
C22 C23 = CMP-001-00103-1: Ceramic Capacitor, Multilayer, Ceramic, 100V, 5% +Tol, 5% -Tol, C0G, -/+30ppm/Cel TC, 0.00022uF, Surface Mount, 0603
D6 = CMP-1426-00005-3: as D4 on sheet 1_STM32
D7 D8 = SD12C-01FTG: TVS Diode (Bi-directional); Manufacturer_Name: LITTELFUSE
IC2 = ADBMS6822WCCSZ: Integrated Circuit; Manufacturer_Name: Analog Devices
R19 = CMP-009-00263-1: as R12 on sheet 1_STM32
R20-R23 = CMP-009-00206-1: Fixed Resistor, Metal Glaze/thick Film, 0.25W, 47ohm, 150V, 5% +/-Tol, 200ppm/Cel, Surface Mount, 0603; Power: 250mW
R24-R27 = CMP-009-00243-1: as R9 on sheet 1_STM32
T1 = 74941300: Transformer; Manufacturer_Name: Wurth Elektronik

## Sheet 3_Current_Sense.SchDoc
size A
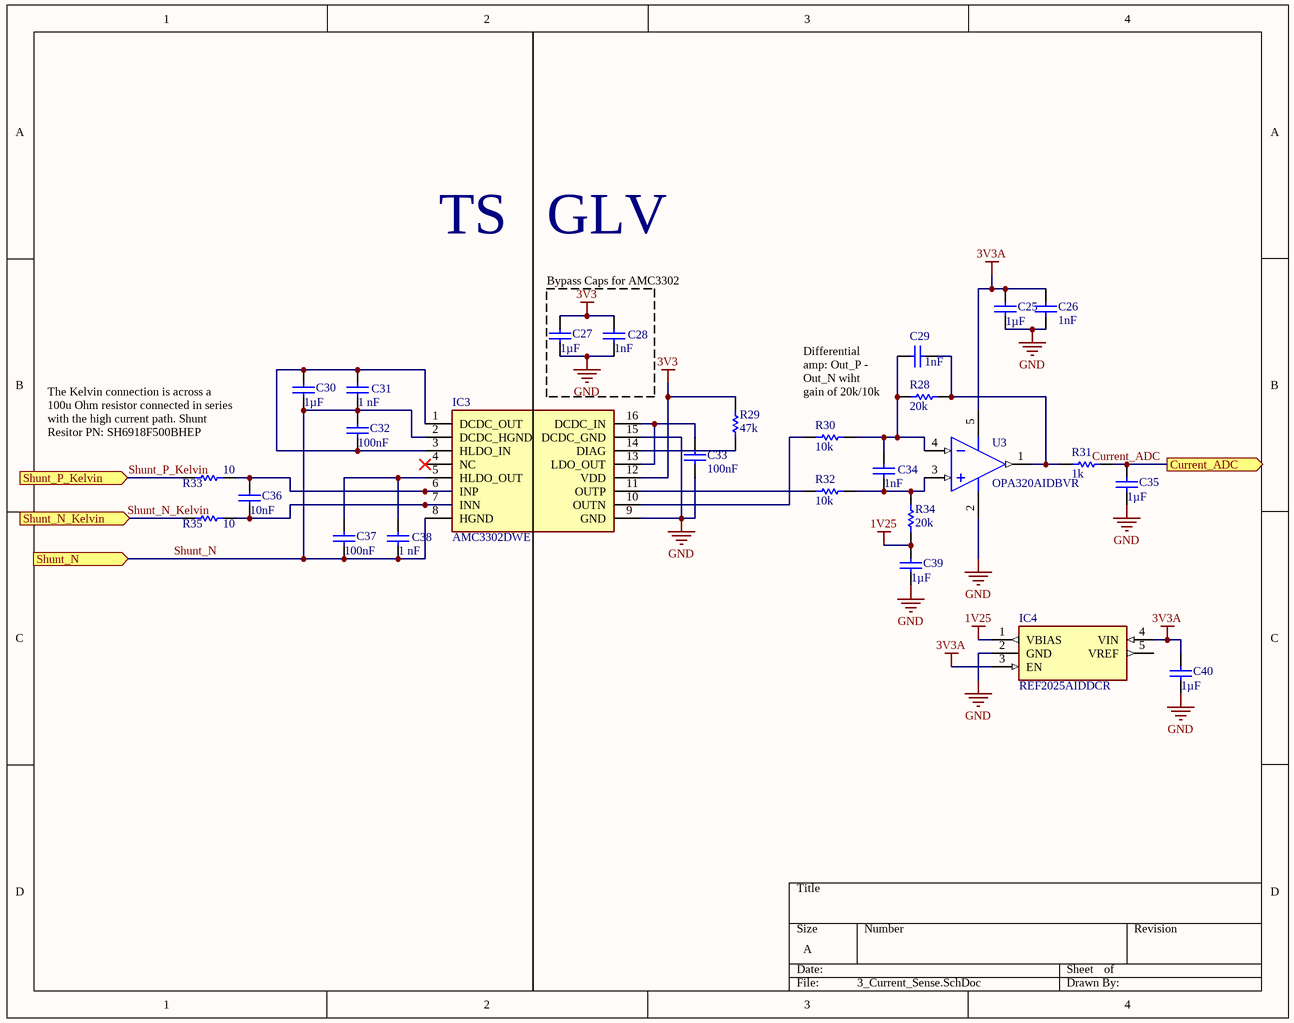
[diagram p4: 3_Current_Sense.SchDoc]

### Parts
C25  value 1µF  [CAPC0603(1608)100_L]  (hidden comment: GRT188R61H105KE13D)
C26  1nF  [CAPC0603(1608)100_L]
C27  value 1µF  [CAPC0603(1608)100_L]  (hidden comment: GRT188R61H105KE13D)
C28  1nF  [CAPC0603(1608)100_L]
C29  1nF  [CAPC0603(1608)100_L]
C30  value 1µF  [CAPC0603(1608)100_L]  (hidden comment: GRT188R61H105KE13D)
C31  1 nF  [CAPC0603(1608)100_L]
C32  value 100nF  [CAPC0603(1608)100_L]  (hidden comment: CGA3E2X7R1H104K080AA)
C33  value 100nF  [CAPC0603(1608)100_L]  (hidden comment: CGA3E2X7R1H104K080AA)
C34  1nF  [CAPC0603(1608)100_L]
C35  value 1µF  [CAPC0603(1608)100_L]  (hidden comment: GRT188R61H105KE13D)
C36  value 10nF  [CAPC0603(1608)100_L]  (hidden comment: GCM188R72A103KA37D)
C37  value 100nF  [CAPC0603(1608)100_L]  (hidden comment: CGA3E2X7R1H104K080AA)
C38  1 nF  [CAPC0603(1608)100_L]
C39  value 1µF  [CAPC0603(1608)100_L]  (hidden comment: GRT188R61H105KE13D)
C40  value 1µF  [CAPC0603(1608)100_L]  (hidden comment: GRT188R61H105KE13D)
IC3  AMC3302DWE  [SOIC127P1030X265-16N]
IC4  REF2025AIDDCR  [SOT95P280X110-5N]
R28  value 20k  [RESC0603(1608)_L]  (hidden comment: ERA-3AEB203V)
R29  value 47k  [RESC0603(1608)_L]  (hidden comment: ERA-3AEB473V)
R30  value 10k  [RESC0603(1608)_L]  (hidden comment: RT0603BRD0710KL)
R31  value 1k  [RESC0603(1608)_L]  (hidden comment: RMCF0603FT1K00)
R32  value 10k  [RESC0603(1608)_L]  (hidden comment: RT0603BRD0710KL)
R33  value 10  [RESC0603(1608)_L]  (hidden comment: RMCF0603FT10R0)
R34  value 20k  [RESC0603(1608)_L]  (hidden comment: ERA-3AEB203V)
R35  value 10  [RESC0603(1608)_L]  (hidden comment: RMCF0603FT10R0)
U3  OPA320AIDBVR  [DBV0005A_L]

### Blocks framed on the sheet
Bypass Caps for AMC3302: C27 C28

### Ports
Current_ADC (out), Shunt_N (in), Shunt_N_Kelvin (in), Shunt_P_Kelvin (in)

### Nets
1V25: C39.2 IC4.1(VBIAS) R34.1
3V3: C27.2 C28.2 IC3.12(VDD) R29.2
3V3A: C25.2 C26.2 C40.2 IC4.3(EN) IC4.4(VIN) U3.5(V+)
GND: C25.1 C26.1 C27.1 C28.1 C33.2 C35.1 C39.1 C40.1 IC3.9(GND) IC3.15(DCDC_GND) IC4.2(GND) U3.2(V-)
Current_ADC: C35.2 R31.1 ; port Current_ADC
Shunt_N: C30.1 C31.1 C32.1 C37.2 C38.1 IC3.2(DCDC_HGND) IC3.8(HGND) ; port Shunt_N
Shunt_N_Kelvin: R35.1 ; port Shunt_N_Kelvin
Shunt_P_Kelvin: R33.1 ; port Shunt_P_Kelvin
NetC29_1: C29.1 C34.2 R28.1 R30.2 U3.4(IN-)
NetC29_2: C29.2 R28.2 R31.2 U3.1(OUT)
NetC30_2: C30.2 C31.2 C32.2 IC3.1(DCDC_OUT) IC3.3(HLDO_IN)
NetC33_1: C33.1 IC3.13(LDO_OUT) IC3.16(DCDC_IN)
NetC34_1: C34.1 R32.2 R34.2 U3.3(IN+)
NetC36_1: C36.1 IC3.7(INN) R35.2
NetC36_2: C36.2 IC3.6(INP) R33.2
NetC37_1: C37.1 C38.2 IC3.5(HLDO_OUT)
NetIC3_10: IC3.10(OUTN) R30.1
NetIC3_11: IC3.11(OUTP) R32.1
NetIC3_14: IC3.14(DIAG) R29.1

Not connected (* = marked no-connect by the designer): IC3 4(NC)*; IC4 5(VREF)

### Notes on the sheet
- TS
- GLV
- The Kelvin connection is across a 100u Ohm resistor connected in series with the high current path. Shunt Resitor PN: SH6918F500BHEP
- Differential amp: Out_P - Out_N wiht gain of 20k/10k

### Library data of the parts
C25 C27 C30 C35 C39 C40 = CMP-001-00128-1: as C8 on sheet 1_STM32
C26 C28 C29 C31 C34 C38 = CMP-001-00094-1: as C9 on sheet 1_STM32
C32 C33 C37 = CMP-001-00125-1: as C1 on sheet 0_ADI_BMS_Main_Overview
C36 = CMP-001-00127-1: Ceramic Capacitor, Multilayer, Ceramic, 100V, 10% +Tol, 10% -Tol, X7R, 15% TC, 0.01uF, Surface Mount, 0603
IC3 = AMC3302DWE: Integrated Circuit; Manufacturer_Name: Texas Instruments
IC4 = REF2025AIDDCR: Integrated Circuit; Manufacturer_Name: Texas Instruments
R28 R34 = CMP-009-00215-1: Fixed Resistor, Thin Film, 0.1W, 20000ohm, 75V, 0.1% +/-Tol, 25ppm/Cel, Surface Mount, 0603; Power: 100mW
R29 = CMP-009-00259-1: as R7 on sheet 1_STM32
R30 R32 = CMP-009-00204-1: as R3 on sheet 1_STM32
R31 = CMP-009-00263-1: as R12 on sheet 1_STM32
R33 R35 = CMP-009-00257-1: as R4 on sheet 1_STM32
U3 = CMP-0272-00853-3: Precision, 20 MHz, 0.9 pA Ib, RRIO, CMOS Operational Amplifier, 1.8 to 5.5 V, -40 to 125 degC, 5-pin SOT23 (DBV5), Green (RoHS & no Sb/Br); Manufacturer: Texas Instruments; Vio (25C)(Max)(mV): 0.15; Number of Channels: 2; Slew Rate(Typ)(V/us): 10; CMRR(Min)(dB): 100; Sub Family: High Output Current Amplifier (>=50mA), Low Input Bias Current Amp (<=10pA), Low Noise Amp (<=10nV/rtHz), Low Offset Voltage Amplifier (<=500uV), Low Supply Voltage Amplifier (<=2.7V), Precision Amplifier; Total Supply Voltage(Min)(+5V is 5, +/-5V is 10): 1.8; Iq per channel(Max)(mA): 1.75; Vn at 1kHz(Typ)(nV/rtHz): 8.5; Offset Drift(Typ)(uV/C): 1.5; IIB(Max)(pA): 0.9; Total Supply Voltage(Max)(+5V is 5, +/-5V is 10): 5.5

## Sheet 5_Vreg.SchDoc
size A
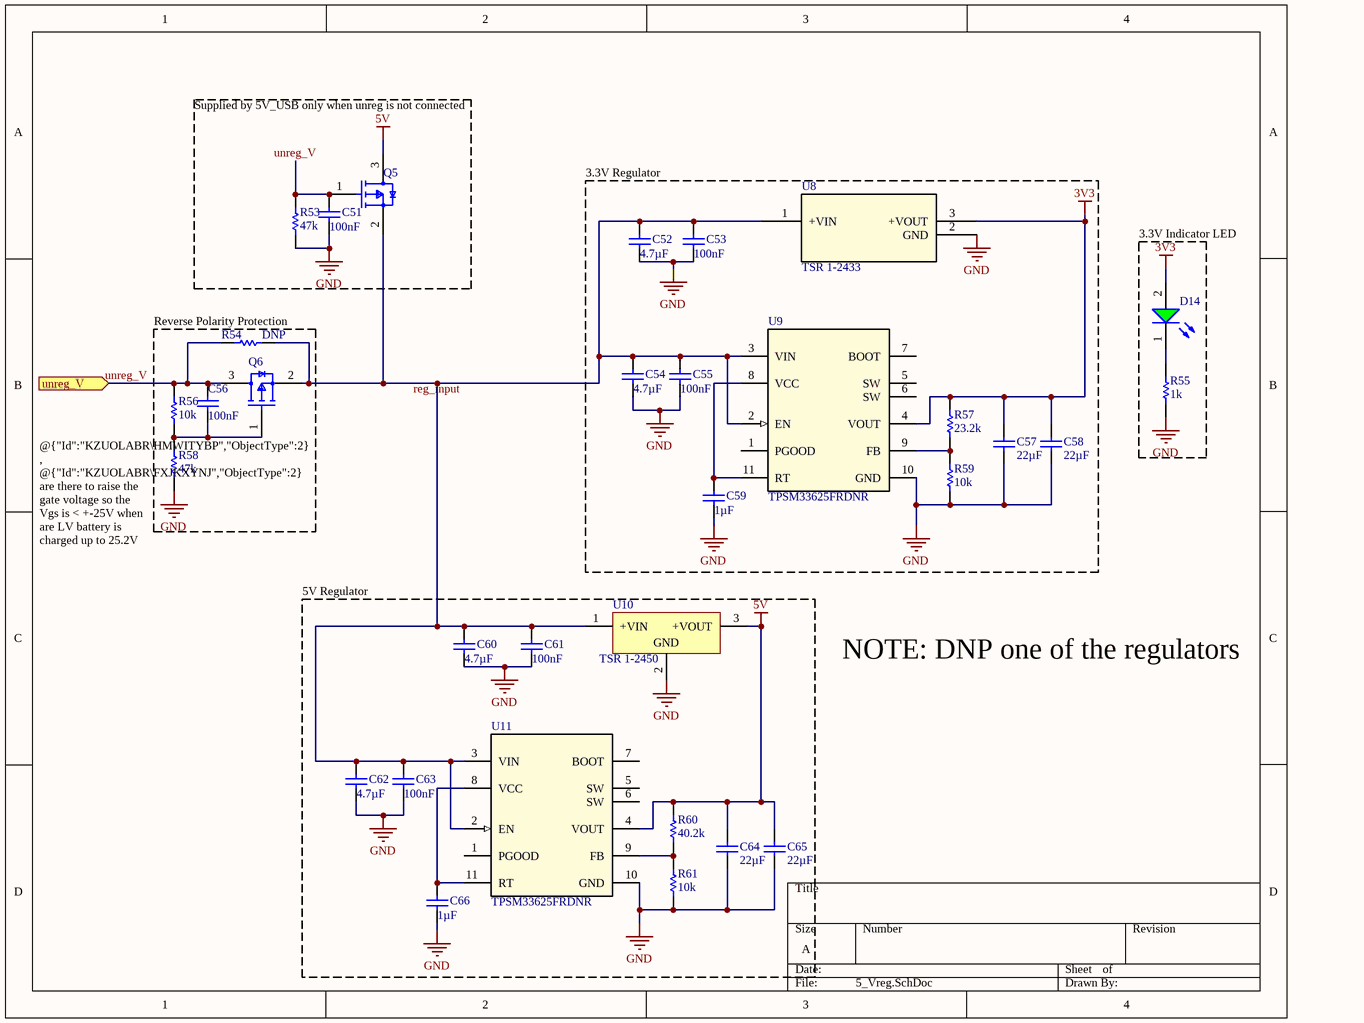
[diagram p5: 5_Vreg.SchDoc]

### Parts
C51  value 100nF  [CAPC0603(1608)100_L]  (hidden comment: CGA3E2X7R1H104K080AA)
C52  value 4.7µF  [CAPC0603(1608)100_L]  (hidden comment: GRT188R6YA475KE13D)
C53  value 100nF  [CAPC0603(1608)100_L]  (hidden comment: CGA3E2X7R1H104K080AA)
C54  value 4.7µF  [CAPC0603(1608)100_L]  (hidden comment: GRT188R6YA475KE13D)
C55  value 100nF  [CAPC0603(1608)100_L]  (hidden comment: CGA3E2X7R1H104K080AA)
C56  value 100nF  [CAPC0603(1608)100_L]  (hidden comment: CGA3E2X7R1H104K080AA)
C57  value 22µF  [CAPC0805(2012)145_L]  (hidden comment: CL21A226MAYNNNE)
C58  value 22µF  [CAPC0805(2012)145_L]  (hidden comment: CL21A226MAYNNNE)
C59  value 1µF  [CAPC0603(1608)100_L]  (hidden comment: GRT188R61H105KE13D)
C60  value 4.7µF  [CAPC0603(1608)100_L]  (hidden comment: GRT188R6YA475KE13D)
C61  value 100nF  [CAPC0603(1608)100_L]  (hidden comment: CGA3E2X7R1H104K080AA)
C62  value 4.7µF  [CAPC0603(1608)100_L]  (hidden comment: GRT188R6YA475KE13D)
C63  value 100nF  [CAPC0603(1608)100_L]  (hidden comment: CGA3E2X7R1H104K080AA)
C64  value 22µF  [CAPC0805(2012)145_L]  (hidden comment: CL21A226MAYNNNE)
C65  value 22µF  [CAPC0805(2012)145_L]  (hidden comment: CL21A226MAYNNNE)
C66  value 1µF  [CAPC0603(1608)100_L]  (hidden comment: GRT188R61H105KE13D)
D14  150060VS75000  [WL-SMCW_0603_150060xx75000]  (value not drawn)
Q5  DMP3056L-7  [FP-SOT23-MFG]  (value not drawn)
Q6  DMP3056L-7  [FP-SOT23-MFG]  (value not drawn)
R53  value 47k  [RESC0603(1608)_L]  (hidden comment: ERA-3AEB473V)
R54  value DNP  [RESC0603(1608)_L]  (hidden comment: RMCF0603ZT0R00)
R55  value 1k  [RESC0603(1608)_L]  (hidden comment: RMCF0603FT1K00)
R56  value 10k  [RESC0603(1608)_L]  (hidden comment: RT0603BRD0710KL)
R57  value 23.2k  [RESC0603(1608)_L]  (hidden comment: RT0603BRD0723K2L)
R58  value 47k  [RESC0603(1608)_L]  (hidden comment: ERA-3AEB473V)
R59  value 10k  [RESC0603(1608)_L]  (hidden comment: RT0603BRD0710KL)
R60  value 40.2k  [RESC0603(1608)_L]  (hidden comment: RT0603BRD0740K2L)
R61  value 10k  [RESC0603(1608)_L]  (hidden comment: RT0603BRD0710KL)
U8  TSR 1-2433  [TSR1-SINGLE_TRP]
U9  TPSM33625FRDNR  [TPSM33625FRDNR]
U10  TSR 1-2450  [TRACO-SIP-3_V]
U11  TPSM33625FRDNR  [TPSM33625FRDNR]

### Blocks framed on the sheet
Supplied by 5V_USB only when unreg is not connected: C51 Q5 R53
3.3V Regulator: C52-C55 C57-C59 R57 R59 U8 U9
3.3V Indicator LED: D14 R55
Reverse Polarity Protection: C56 Q6 R54 R56 R58
5V Regulator: C60-C66 R60 R61 U10 U11

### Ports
unreg_V (in)

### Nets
3V3: C57.2 C58.2 D14.2(A) R57.2 U8.3(+VOUT) U9.4(VOUT)
5V: C64.2 C65.2 Q5.3(D) R60.2 U10.3(+VOUT) U11.4(VOUT)
GND: C51.2 C52.1 C53.2 C54.1 C55.2 C57.1 C58.1 C59.1 C60.1 C61.2 C62.1 C63.2 C64.1 C65.1 C66.1 R53.1 R55.1 R58.1 R59.1 R61.1 U8.2(GND) U9.10(GND) U10.2(GND) U11.10(GND)
reg_input: C52.2 C53.1 C54.2 C55.1 C60.2 C61.1 C62.2 C63.1 Q5.2(S) Q6.2(S) R54.1 U8.1(+VIN) U9.2(EN) U9.3(VIN) U10.1(+VIN) U11.2(EN) U11.3(VIN)
unreg_V: C51.1 C56.1 Q5.1(G) Q6.3(D) R53.2 R54.2 R56.2 ; port unreg_V
NetC56_2: C56.2 Q6.1(G) R56.1 R58.2
NetC59_2: C59.2 U9.8(VCC) U9.11(RT)
NetC66_2: C66.2 U11.8(VCC) U11.11(RT)
NetD14_1: D14.1(K) R55.2
NetR57_1: R57.1 R59.2 U9.9(FB)
NetR60_1: R60.1 R61.2 U11.9(FB)

Not connected (* = marked no-connect by the designer): U9 1(PGOOD) 5(SW) 6(SW) 7(BOOT); U11 1(PGOOD) 5(SW) 6(SW) 7(BOOT)

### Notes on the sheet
- @{"Id":"KZUOLABR\HMWITYBP","ObjectType":2} , @{"Id":"KZUOLABR\FXJKXYNJ","ObjectType":2} are there to raise the gate voltage so the Vgs is < +-25V when are LV battery is charged up to 25.2V
- NOTE: DNP one of the regulators

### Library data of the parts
C51 C53 C55 C56 C61 C63 = CMP-001-00125-1: as C1 on sheet 0_ADI_BMS_Main_Overview
C52 C54 C60 C62 = CMP-001-00126-1: as C2 on sheet 1_STM32
C57 C58 C64 C65 = CMP-001-00132-1: Ceramic Capacitor, Multilayer, Ceramic, 25V, 20% +Tol, 20% -Tol, X5R, 15% TC, 22uF, Surface Mount, 0805
C59 C66 = CMP-001-00128-1: as C8 on sheet 1_STM32
D14 = CMP-1426-00006-7: as D1 on sheet 1_STM32
Q5 Q6 = CMP-12801-000002-1: as Q1 on sheet 4_Contactor_Ctrl
R53 R58 = CMP-009-00259-1: as R7 on sheet 1_STM32
R54 = CMP-009-00243-1: as R9 on sheet 1_STM32
R55 = CMP-009-00263-1: as R12 on sheet 1_STM32
R56 R59 R61 = CMP-009-00204-1: as R3 on sheet 1_STM32
R57 = CMP-009-00267-1: Fixed Resistor, Thin Film, 0.1W, 23200ohm, 75V, 0.1% +/-Tol, 25ppm/Cel, Surface Mount, 0603; Power: 100mW
R60 = CMP-009-00266-1: Fixed Resistor, Thin Film, 0.1W, 40200ohm, 75V, 0.1% +/-Tol, 25ppm/Cel, Surface Mount, 0603; Power: 100mW
U8 = CMP-2000-05426-2: NexarPartId: 9539342; Nominal Output Voltage: 3.3V; Max Input Voltage: 36V; Max Output Power: 3.3W; Min Input Voltage: 4.75V; Nominal Supply Current: 1mA; Output Type: Fixed; Max Output Current: 1A; Min Input Voltage (DC): 5.5V; Efficiency: 79%; Number of Outputs: 1; Isolation: Isolated; Max Input Voltage (DC): 32V; Switching Frequency: 500kHz
U9 U11 = TPSM33625FRDNR: No Description Available; Mfr_Name: Texas Instruments
U10 = CMP-2000-05427-1: DC/DC converter, 5 VDC, 1000 mA, -40 to 85 degC, 3-Pin SIP, RoHS; Manufacturer: Tracopower; Output Voltage Nom.: 5V; Output Current Max: 1A; Product Range: TSR-1Series; DC / DC Converter Mounting: ThroughHole; Output Power Max: 5W; No. of Outputs: 1Output; Input Voltage DC Max: 36V; Approvals & Standards: IEC,UL; Input Voltage DC Min: 6.5V; DC / DC Converter Output Type: Fixed

## Sheet 6_CAN.SchDoc
size A
Used 2 times, as channels Drive, DATA. Parts and nets are listed once, with the designators drawn on the sheet.
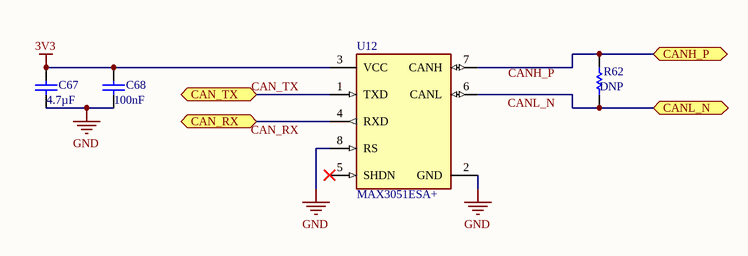
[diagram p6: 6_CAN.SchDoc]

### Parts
C67  value 4.7µF  [CAPC0603(1608)100_L]  (hidden comment: GRT188R6YA475KE13D)
C68  value 100nF  [CAPC0603(1608)100_L]  (hidden comment: CGA3E2X7R1H104K080AA)
R62  DNP  [RESC0603(1608)_L]
U12  MAX3051ESA+  [FP-S8-4-MFG]

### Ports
CAN_RX (bidir), CAN_TX (bidir), CANH_P (bidir), CANL_N (bidir)

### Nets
3V3: C67.2 C68.1 U12.3(VCC)
GND: C67.1 C68.2 U12.2(GND) U12.8(RS)
CAN_RX: U12.4(RXD) ; port CAN_RX
CAN_TX: U12.1(TXD) ; port CAN_TX
CANH_P: R62.2 U12.7(CANH) ; port CANH_P
CANL_N: R62.1 U12.6(CANL) ; port CANL_N

Not connected (* = marked no-connect by the designer): U12 5(SHDN)*

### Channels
Drive: designators end in _Drive; ports CAN_RX=CAN_RX CAN_TX=CAN_TX CANH_P=CANH_Drive_P CANL_N=CANL_Drive_N
DATA: designators end in _DATA; ports CAN_RX=CAN_RX CAN_TX=CAN_TX CANH_P=CANH_Data_P CANL_N=CANL_Data_N

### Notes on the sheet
- Labels drawn without touching a wire or pin: CANH_P

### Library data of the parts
C67 = CMP-001-00126-1: as C2 on sheet 1_STM32
C68 = CMP-001-00125-1: as C1 on sheet 0_ADI_BMS_Main_Overview
R62 = CMP-009-00223-1: Fixed Resistor, Metal Glaze/thick Film, 0.1W, 120ohm, 75V, 1% +/-Tol, 100ppm/Cel, Surface Mount, 0603, RMCF0603FT120R; Value: 120; Power: 100mW
U12 = CMP-05676-000001-1: IC TXRX CAN 1MBPS 8-SOIC; Manufacturer: Maxim Integrated; Nominal Supply Current: 8-35000uA; Min Supply Voltage: 3.14V; Max Supply Voltage: 3.47V; Max Junction Temp: +150°C; Standoff Height: 0.1mm

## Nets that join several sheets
3V3: 0_ADI_BMS_Main_Overview (J2.1 U1.1 U1.5), 1_STM32 (13 pins), 2_ADI_Comms (7 pins), 3_Current_Sense (C27.2 C28.2 IC3.12 R29.2), 5_Vreg (6 pins), Drive (C67_Drive.2 C68_Drive.1 U12_Drive.3), DATA (C67_DATA.2 C68_DATA.1 U12_DATA.3)
3V3A: 1_STM32 (C8.2 C9.2 L1.2 U2.13), 3_Current_Sense (6 pins)
5V: 0_ADI_BMS_Main_Overview (IC1.5 P1.1 U1.6), 2_ADI_Comms (8 pins), 5_Vreg (6 pins)
GND: 0_ADI_BMS_Main_Overview (6 pins), 1_STM32 (30 pins), 4_Contactor_Ctrl (21 pins), 2_ADI_Comms (14 pins), 3_Current_Sense (12 pins), 5_Vreg (24 pins), Drive (C67_Drive.1 C68_Drive.2 U12_Drive.2 U12_Drive.8), DATA (C67_DATA.1 C68_DATA.2 U12_DATA.2 U12_DATA.8)
6822_State: 1_STM32 (TP5.1 U2.36), 2_ADI_Comms (IC2.8)
BMS_SD_IN: 0_ADI_BMS_Main_Overview (J1.5), 4_Contactor_Ctrl (C43.2 Q2.2 R39.2)
BMS_SD_OUT: 0_ADI_BMS_Main_Overview (J1.1), 4_Contactor_Ctrl (Q2.3)
BMS_Status: 0_ADI_BMS_Main_Overview (U1.3), 1_STM32 (D1.2 U2.40), 4_Contactor_Ctrl (C45.2 R42.2 U5.1)
CAN_RX: 1_STM32 (U2.33), DATA (U12_DATA.4)
CAN_RX: 1_STM32 (U2.61), Drive (U12_Drive.4)
CAN_TX: 1_STM32 (U2.34), DATA (U12_DATA.1)
CAN_TX: 1_STM32 (U2.62), Drive (U12_Drive.1)
CANH_Data_P: 0_ADI_BMS_Main_Overview (J1.10), DATA (R62_DATA.2 U12_DATA.7)
CANH_Drive_P: 0_ADI_BMS_Main_Overview (J1.7), Drive (R62_Drive.2 U12_Drive.7)
CANL_Data_N: 0_ADI_BMS_Main_Overview (J1.11), DATA (R62_DATA.1 U12_DATA.6)
CANL_Drive_N: 0_ADI_BMS_Main_Overview (J1.8), Drive (R62_Drive.1 U12_Drive.6)
Charger: 0_ADI_BMS_Main_Overview (J1.13), 1_STM32 (R7.2)
Contactor_N: 0_ADI_BMS_Main_Overview (J1.2), 4_Contactor_Ctrl (D9.1 D11.2 Q1.3)
Contactor_N_ctr: 1_STM32 (U2.41), 4_Contactor_Ctrl (C44.2 R40.2 U4.1)
Contactor_P: 0_ADI_BMS_Main_Overview (J1.3), 4_Contactor_Ctrl (D10.1 D12.2 Q3.3)
Contactor_P_ctrl: 1_STM32 (U2.42), 4_Contactor_Ctrl (C48.2 R46.2 U6.1)
Contactor_Pre: 0_ADI_BMS_Main_Overview (J1.4), 4_Contactor_Ctrl (D13.2 Q4.3)
Contactor_Pre_ctr: 1_STM32 (U2.43), 4_Contactor_Ctrl (C50.2 R52.2 U7.1)
CSB: 1_STM32 (R3.1 TP4.1 U2.20), 2_ADI_Comms (D6.1 IC2.5)
Current_ADC: 1_STM32 (U2.16), 3_Current_Sense (C35.2 R31.1)
IM_Out: 0_ADI_BMS_Main_Overview (J3.1), 2_ADI_Comms (T1.4)
IMD_Status: 0_ADI_BMS_Main_Overview (J1.12), 1_STM32 (R14.2)
IP_Out: 0_ADI_BMS_Main_Overview (J3.3), 2_ADI_Comms (T1.6)
MISO: 1_STM32 (R5.1 TP2.1), 2_ADI_Comms (IC2.3)
MOSI: 1_STM32 (R6.1 TP1.1), 2_ADI_Comms (IC2.2)
NRST: 0_ADI_BMS_Main_Overview (J2.2), 1_STM32 (C13.1 U2.7)
SCK: 1_STM32 (R4.1 TP3.1), 2_ADI_Comms (IC2.4)
SD_Contactors: 0_ADI_BMS_Main_Overview (J1.6), 1_STM32 (D3.2 R10.1), 4_Contactor_Ctrl (13 pins)
Shunt_N: 0_ADI_BMS_Main_Overview (J4.3), 3_Current_Sense (7 pins)
Shunt_N_Kelvin: 0_ADI_BMS_Main_Overview (J4.2), 3_Current_Sense (R35.1)
Shunt_P_Kelvin: 0_ADI_BMS_Main_Overview (J4.1), 3_Current_Sense (R33.1)
SWCLK: 0_ADI_BMS_Main_Overview (J2.5), 1_STM32 (U2.49)
SWDIO: 0_ADI_BMS_Main_Overview (J2.4), 1_STM32 (U2.46)
SWO: 0_ADI_BMS_Main_Overview (J2.3), 1_STM32 (U2.55)
unreg_V: 0_ADI_BMS_Main_Overview (J1.15), 5_Vreg (7 pins)
USB_D_N: 0_ADI_BMS_Main_Overview (IC1.4), 1_STM32 (U2.44)
USB_D_P: 0_ADI_BMS_Main_Overview (IC1.6), 1_STM32 (U2.45)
